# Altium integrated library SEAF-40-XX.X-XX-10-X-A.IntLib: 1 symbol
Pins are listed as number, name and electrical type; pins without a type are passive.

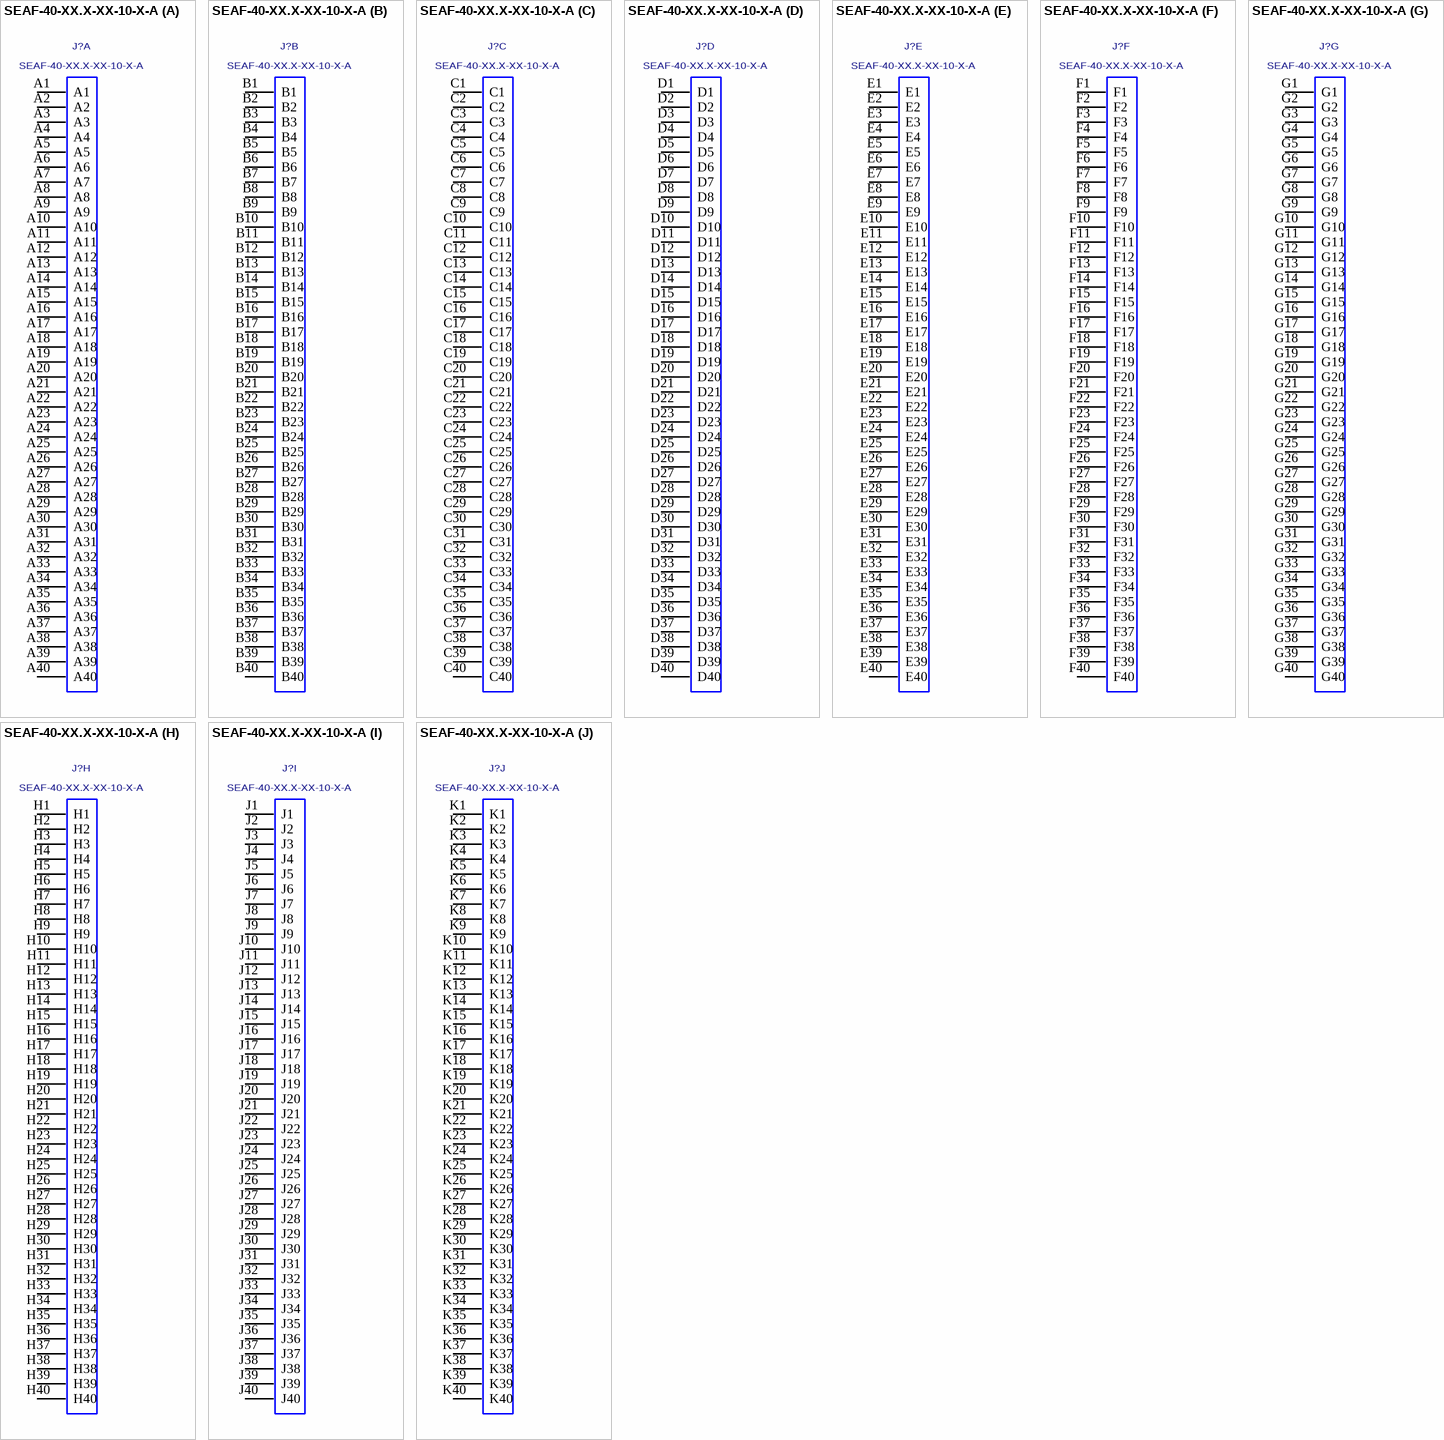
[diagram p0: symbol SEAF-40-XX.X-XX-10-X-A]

## SEAF-40-XX.X-XX-10-X-A
designator J?
Socket Array Assembly, Surface Mount, 0.050" Pitch, 400 Pins; MANUFACTURER: SAMTEC
footprint SEAF-40-XX.X-XX-10-X-A
part A pins: A1, A2, A3, A4, A5, A6, A7, A8, A9, A10, A11, A12, A13, A14, A15, A16, A17, A18, A19, A20, A21, A22, A23, A24, A25, A26, A27, A28, A29, A30, A31, A32, A33, A34, A35, A36, A37, A38, A39, A40
part B pins: B1, B2, B3, B4, B5, B6, B7, B8, B9, B10, B11, B12, B13, B14, B15, B16, B17, B18, B19, B20, B21, B22, B23, B24, B25, B26, B27, B28, B29, B30, B31, B32, B33, B34, B35, B36, B37, B38, B39, B40
part C pins: C1, C2, C3, C4, C5, C6, C7, C8, C9, C10, C11, C12, C13, C14, C15, C16, C17, C18, C19, C20, C21, C22, C23, C24, C25, C26, C27, C28, C29, C30, C31, C32, C33, C34, C35, C36, C37, C38, C39, C40
part D pins: D1, D2, D3, D4, D5, D6, D7, D8, D9, D10, D11, D12, D13, D14, D15, D16, D17, D18, D19, D20, D21, D22, D23, D24, D25, D26, D27, D28, D29, D30, D31, D32, D33, D34, D35, D36, D37, D38, D39, D40
part E pins: E1, E2, E3, E4, E5, E6, E7, E8, E9, E10, E11, E12, E13, E14, E15, E16, E17, E18, E19, E20, E21, E22, E23, E24, E25, E26, E27, E28, E29, E30, E31, E32, E33, E34, E35, E36, E37, E38, E39, E40
part F pins: F1, F2, F3, F4, F5, F6, F7, F8, F9, F10, F11, F12, F13, F14, F15, F16, F17, F18, F19, F20, F21, F22, F23, F24, F25, F26, F27, F28, F29, F30, F31, F32, F33, F34, F35, F36, F37, F38, F39, F40
part G pins: G1, G2, G3, G4, G5, G6, G7, G8, G9, G10, G11, G12, G13, G14, G15, G16, G17, G18, G19, G20, G21, G22, G23, G24, G25, G26, G27, G28, G29, G30, G31, G32, G33, G34, G35, G36, G37, G38, G39, G40
part H pins: H1, H2, H3, H4, H5, H6, H7, H8, H9, H10, H11, H12, H13, H14, H15, H16, H17, H18, H19, H20, H21, H22, H23, H24, H25, H26, H27, H28, H29, H30, H31, H32, H33, H34, H35, H36, H37, H38, H39, H40
part I pins: J1, J2, J3, J4, J5, J6, J7, J8, J9, J10, J11, J12, J13, J14, J15, J16, J17, J18, J19, J20, J21, J22, J23, J24, J25, J26, J27, J28, J29, J30, J31, J32, J33, J34, J35, J36, J37, J38, J39, J40
part J pins: K1, K2, K3, K4, K5, K6, K7, K8, K9, K10, K11, K12, K13, K14, K15, K16, K17, K18, K19, K20, K21, K22, K23, K24, K25, K26, K27, K28, K29, K30, K31, K32, K33, K34, K35, K36, K37, K38, K39, K40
